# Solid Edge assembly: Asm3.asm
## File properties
Author: Impact Mechanic Lab
Template: Iso Metric Assembly.asm
Last saved by: Impact Mechanic Lab
Revision: 3
Application: Solid Edge
Username: Impact Mechanic Lab
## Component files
Handle_cover.par
Body.par
spindle.par
Ball.par
End_flange.par
Top_cover.par
Handle.par
Nut.par
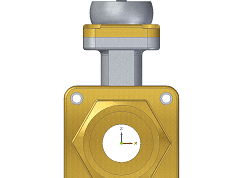
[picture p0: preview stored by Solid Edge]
